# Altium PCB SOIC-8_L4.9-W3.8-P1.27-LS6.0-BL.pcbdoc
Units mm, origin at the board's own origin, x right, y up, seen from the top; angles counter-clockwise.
Board outline 18.03 x 20.29 mm, 2 copper layers (Top Layer, Bottom Layer), stack 0 mm thick; 1 components, 0 nets, 8 pads, 0 vias.
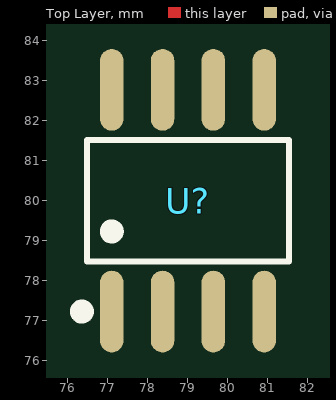
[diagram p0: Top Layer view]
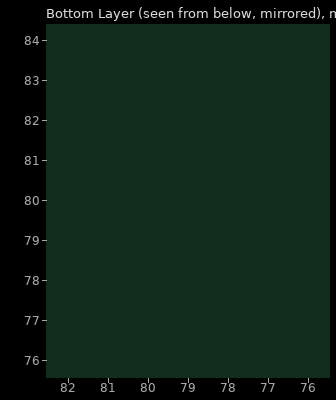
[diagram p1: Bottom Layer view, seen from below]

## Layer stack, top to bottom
Top Layer: signal copper (thickness not stored)
Bottom Layer: signal copper (thickness not stored)

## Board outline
87.878,69.85 69.85,69.85 69.85,90.14 87.878,90.14

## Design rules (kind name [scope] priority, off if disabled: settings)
PasteMaskExpansion "Paste Mask Expansion" [All] p1: expansion=0
SolderMaskExpansion "Solder Mask Expansion" [IsVia] p1: expansion=-25.4 istentingtop=TRUE
SolderMaskExpansion "Solder Mask Expansion" [All] p2: expansion=0.051 istentingtop=FALSE

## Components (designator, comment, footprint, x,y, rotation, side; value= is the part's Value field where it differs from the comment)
U? "" SOIC-8_L4.9-W3.8-P1.27-LS6.0-BL 79.002,79.995 r0 top

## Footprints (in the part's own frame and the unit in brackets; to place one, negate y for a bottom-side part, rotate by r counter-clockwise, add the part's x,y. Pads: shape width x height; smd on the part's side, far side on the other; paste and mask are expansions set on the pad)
SOIC-8_L4.9-W3.8-P1.27-LS6.0-BL [mm]
  oval 0.588x2.045 smd: 1(-1.905,-2.772) 2(-0.635,-2.772) 3(0.635,-2.772) 4(1.905,-2.772) 5(1.905,2.772) 6(0.635,2.772) 7(-0.635,2.772) 8(-1.905,2.772)
  silkscreen extent -2.8,-2.92 2.53,1.52

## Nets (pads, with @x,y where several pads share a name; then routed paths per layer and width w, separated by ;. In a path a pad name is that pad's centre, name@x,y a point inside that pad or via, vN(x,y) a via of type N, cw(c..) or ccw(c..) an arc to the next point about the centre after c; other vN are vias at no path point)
pads on no net: U?.1 U?.2 U?.3 U?.4 U?.5 U?.6 U?.7 U?.8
